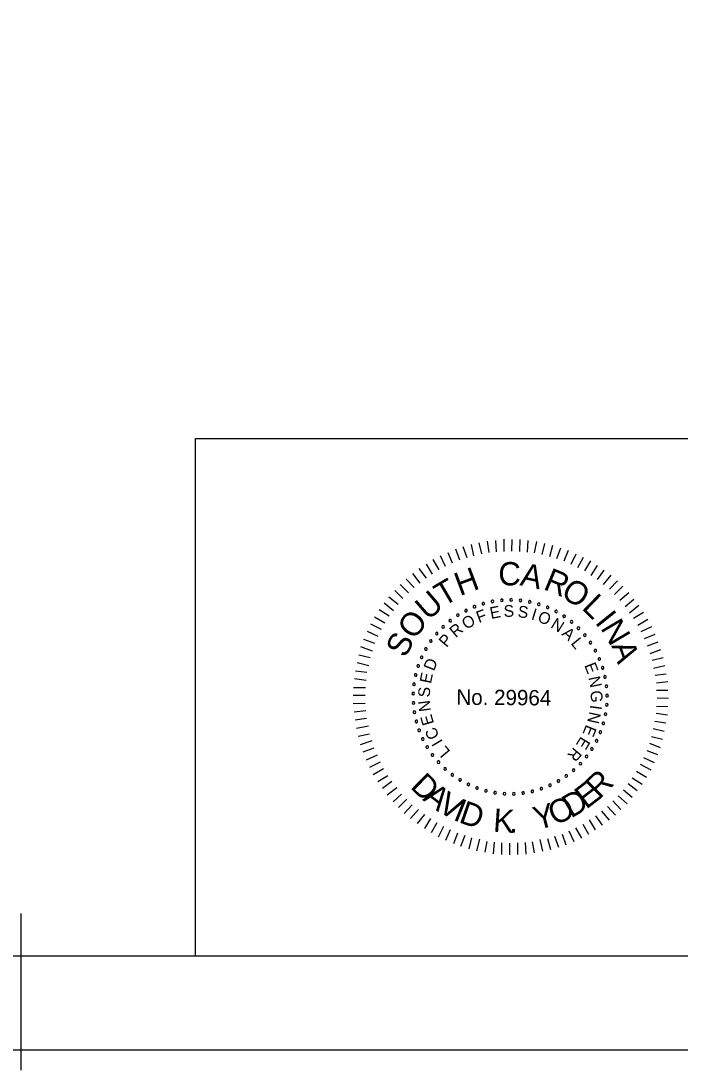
# Model space of a CAD drawing. Extents: x -133.1 to -97, y -1.8 to 20.5.
# Drawn here: x -111.44 to -107.93, y -1.8 to 3.78 of the extents above; entities that cross this region are included whole.
import ezdxf

# ---------------------------------------------------------------- set-up
doc = ezdxf.new("R2010")
doc.units = 0
for name, color, linetype in [('BR_BORDER LINES', 7, 'Continuous'), ('BR_TEXT', 7, 'Continuous'), ('Level 31', 7, 'Continuous')]:
    doc.layers.add(name, color=color, linetype=linetype)

msp = doc.modelspace()

# ---------------------------------------------------------------- linework, layer by layer
at = {"layer": 'BR_BORDER LINES'}
for p, q in [((-110.5071, 1.5591), (-105.1419, 1.5591)), ((-110.5071, -1.191), (-110.5071, 1.5591)), ((-131.3076, -1.191), (-97.6416, -1.191))]:
    msp.add_line(p, q, dxfattribs=at)
at = {"layer": 'BR_TEXT'}
for p, q in [((-108.9849, 0.9447), (-108.999, 1.0041)), ((-108.9454, 0.9521), (-108.9543, 1.0131)), ((-108.9059, 0.9561), (-108.9097, 1.017)), ((-108.8664, 0.9584), (-108.8658, 1.0227)), ((-108.8243, 0.9606), (-108.8238, 1.0224)), ((-108.7823, 0.9577), (-108.78, 1.022)), ((-108.742, 0.9548), (-108.7372, 1.0156)), ((-108.7034, 0.9501), (-108.6926, 1.011)), ((-109.1406, 0.8954), (-109.1642, 0.9514)), ((-109.1019, 0.9122), (-109.1229, 0.9708)), ((-109.0623, 0.9248), (-109.0842, 0.9824)), ((-109.0262, 0.9348), (-109.0394, 0.9958)), ((-108.6631, 0.9421), (-108.6489, 1.0012)), ((-108.622, 0.9314), (-108.606, 0.9922)), ((-108.5852, 0.9208), (-108.5633, 0.9781)), ((-108.5458, 0.9076), (-108.5239, 0.9658)), ((-109.2122, 0.8608), (-109.2426, 0.9151)), ((-109.1777, 0.8785), (-109.2039, 0.9345)), ((-108.5099, 0.8902), (-108.482, 0.9457)), ((-108.474, 0.8727), (-108.4427, 0.9282)), ((-108.4364, 0.8544), (-108.4042, 0.9082)), ((-109.3123, 0.7904), (-109.3522, 0.8405)), ((-109.2786, 0.8159), (-109.3177, 0.8668)), ((-109.2475, 0.8371), (-109.278, 0.8914)), ((-108.4031, 0.8301), (-108.3692, 0.8839)), ((-108.3699, 0.8083), (-108.3334, 0.8587)), ((-109.3745, 0.7386), (-109.4188, 0.7827)), ((-109.3451, 0.7658), (-109.3868, 0.8107)), ((-108.3375, 0.7824), (-108.2968, 0.8318)), ((-108.3059, 0.7572), (-108.2627, 0.8014)), ((-109.4039, 0.7079), (-109.4474, 0.7503)), ((-108.2779, 0.7295), (-108.2346, 0.7729)), ((-108.2498, 0.6984), (-108.2022, 0.74)), ((-109.4551, 0.6431), (-109.5046, 0.683)), ((-109.4291, 0.6763), (-109.4786, 0.7154)), ((-108.2226, 0.6664), (-108.1759, 0.7046)), ((-108.1988, 0.6327), (-108.1496, 0.6718)), ((-109.4768, 0.6141), (-109.5306, 0.6472)), ((-108.1768, 0.6034), (-108.1242, 0.6355)), ((-109.5186, 0.5432), (-109.575, 0.5711)), ((-109.5012, 0.5774), (-109.5549, 0.6096)), ((-108.1548, 0.5663), (-108.1013, 0.5976)), ((-108.137, 0.5318), (-108.0793, 0.5588)), ((-109.5361, 0.5065), (-109.5933, 0.5318)), ((-108.1193, 0.4948), (-108.0624, 0.5192)), ((-109.5659, 0.4278), (-109.6275, 0.4506)), ((-109.5536, 0.468), (-109.6117, 0.4899)), ((-108.1025, 0.456), (-108.0456, 0.477)), ((-109.5782, 0.3918), (-109.639, 0.4069)), ((-108.0891, 0.4156), (-108.0314, 0.4374)), ((-108.079, 0.3794), (-108.0189, 0.3935)), ((-109.5854, 0.3498), (-109.6479, 0.3658)), ((-108.0708, 0.3373), (-108.0106, 0.3522)), ((-109.6006, 0.2727), (-109.6624, 0.2801)), ((-109.596, 0.3138), (-109.6569, 0.3221)), ((-108.0625, 0.3012), (-108.0033, 0.3084)), ((-109.6035, 0.2333), (-109.6679, 0.2338)), ((-108.056, 0.26), (-107.995, 0.2663)), ((-109.6056, 0.1921), (-109.6682, 0.1926)), ((-108.0546, 0.2205), (-107.9945, 0.22)), ((-108.0524, 0.1793), (-107.9915, 0.1788)), ((-109.6042, 0.1492), (-109.6686, 0.148)), ((-108.0553, 0.1364), (-107.9952, 0.1342)), ((-109.602, 0.1105), (-109.6638, 0.1033)), ((-109.598, 0.0693), (-109.659, 0.0604)), ((-108.0645, 0.0566), (-108.0054, 0.0467)), ((-108.0574, 0.0978), (-107.9965, 0.0896)), ((-109.5881, 0.0297), (-109.6508, 0.0165)), ((-108.0735, 0.0172), (-108.0135, 0.003)), ((-109.5815, -0.0124), (-109.6426, -0.0265)), ((-109.5698, -0.0493), (-109.6318, -0.0703)), ((-108.0824, -0.0248), (-108.0224, -0.0398)), ((-109.5582, -0.0881), (-109.6167, -0.1091)), ((-108.107, -0.1001), (-108.0506, -0.122)), ((-108.093, -0.0615), (-108.0357, -0.0835)), ((-109.5413, -0.1251), (-109.599, -0.1521)), ((-109.5244, -0.1613), (-109.5813, -0.1909)), ((-108.1245, -0.1368), (-108.0681, -0.1647)), ((-109.5076, -0.1984), (-109.5619, -0.2297)), ((-108.1612, -0.2095), (-108.1082, -0.2417)), ((-108.1428, -0.1727), (-108.0856, -0.2032)), ((-109.4838, -0.2355), (-109.5382, -0.2668)), ((-109.4626, -0.2648), (-109.5127, -0.3013)), ((-108.2063, -0.2752), (-108.1577, -0.3125)), ((-108.1838, -0.2462), (-108.1317, -0.2784)), ((-109.4372, -0.2985), (-109.4873, -0.3376)), ((-109.4125, -0.3321), (-109.4567, -0.373)), ((-108.2306, -0.3084), (-108.1846, -0.3483)), ((-109.3836, -0.3582), (-109.4286, -0.4032)), ((-109.3547, -0.3884), (-109.3971, -0.4344)), ((-108.2869, -0.3672), (-108.2444, -0.413)), ((-108.2583, -0.3417), (-108.2115, -0.3833)), ((-109.3222, -0.4144), (-109.363, -0.4613)), ((-109.289, -0.4404), (-109.3289, -0.4882)), ((-108.3474, -0.4225), (-108.3075, -0.47)), ((-108.3155, -0.397), (-108.273, -0.4437)), ((-109.2583, -0.4622), (-109.2896, -0.5142)), ((-109.2233, -0.4847), (-109.2546, -0.5386)), ((-108.4475, -0.4911), (-108.4162, -0.5455)), ((-108.4139, -0.4691), (-108.3808, -0.5217)), ((-108.3802, -0.448), (-108.3446, -0.4963)), ((-109.1891, -0.5048), (-109.2162, -0.5603)), ((-109.1523, -0.5222), (-109.1769, -0.5778)), ((-109.1139, -0.5397), (-109.1358, -0.5962)), ((-109.0745, -0.552), (-109.0973, -0.6102)), ((-108.5974, -0.556), (-108.5764, -0.6145)), ((-108.5578, -0.5443), (-108.5368, -0.6011)), ((-108.5216, -0.5274), (-108.4947, -0.5835)), ((-108.4855, -0.5106), (-108.455, -0.5666)), ((-109.0386, -0.5644), (-109.0528, -0.6235)), ((-108.9974, -0.5716), (-109.0126, -0.6333)), ((-108.9581, -0.5831), (-108.968, -0.6413)), ((-108.9186, -0.5877), (-108.9234, -0.6494)), ((-108.8792, -0.5906), (-108.8797, -0.6524)), ((-108.8372, -0.5935), (-108.8377, -0.6544)), ((-108.7951, -0.5913), (-108.7939, -0.6531)), ((-108.7547, -0.589), (-108.7509, -0.6509)), ((-108.7161, -0.5851), (-108.7062, -0.6435)), ((-108.6756, -0.5742), (-108.6624, -0.6361)), ((-108.6344, -0.5677), (-108.6194, -0.627))]:
    msp.add_line(p, q, dxfattribs=at)
for centre, start, end in [((-109.0235, 0.6646), 21.6807, 201.6807), ((-108.9763, 0.6806), 16.1422, 196.1422), ((-108.9763, 0.6806), 196.1422, 16.1422), ((-108.9278, 0.692), 10.6038, 190.6038), ((-108.9278, 0.692), 190.6038, 10.6038), ((-108.8784, 0.6987), 5.0653, 185.0653), ((-108.8784, 0.6987), 185.0653, 5.0653), ((-108.8286, 0.7006), 359.5268, 179.5268), ((-108.8286, 0.7006), 179.5268, 359.5268), ((-108.7789, 0.6977), 173.9884, 353.9884), ((-108.7789, 0.6977), 353.9884, 173.9884), ((-108.7296, 0.69), 168.4499, 348.4499), ((-108.7296, 0.69), 348.4499, 168.4499), ((-108.6814, 0.6776), 162.9114, 342.9114), ((-108.6814, 0.6776), 342.9114, 162.9114), ((-109.1121, 0.6192), 32.7576, 212.7576), ((-109.1121, 0.6192), 212.7576, 32.7576), ((-109.0689, 0.644), 27.2191, 207.2191), ((-109.0689, 0.644), 207.2191, 27.2191), ((-109.0235, 0.6646), 201.6807, 21.6807), ((-108.6345, 0.6606), 157.373, 337.373), ((-108.6345, 0.6606), 337.373, 157.373), ((-108.5896, 0.6391), 151.8345, 331.8345), ((-108.5896, 0.6391), 331.8345, 151.8345), ((-108.5469, 0.6134), 146.2961, 326.2961), ((-108.5469, 0.6134), 326.2961, 146.2961), ((-109.1903, 0.5577), 43.8345, 223.8345), ((-109.1903, 0.5577), 223.8345, 43.8345), ((-109.1527, 0.5903), 38.2961, 218.2961), ((-109.1527, 0.5903), 218.2961, 38.2961), ((-108.5069, 0.5837), 140.7576, 320.7576), ((-108.5069, 0.5837), 320.7576, 140.7576), ((-109.2246, 0.5215), 49.373, 229.373), ((-109.2246, 0.5215), 229.373, 49.373), ((-108.4699, 0.5503), 135.2191, 315.2191), ((-108.4699, 0.5503), 315.2191, 135.2191), ((-108.4363, 0.5134), 129.6807, 309.6807), ((-108.4363, 0.5134), 309.6807, 129.6807), ((-109.282, 0.4402), 60.4499, 240.4499), ((-109.282, 0.4402), 240.4499, 60.4499), ((-109.2553, 0.4822), 54.9114, 234.9114), ((-109.2553, 0.4822), 234.9114, 54.9114), ((-108.4065, 0.4735), 124.1422, 304.1422), ((-108.4065, 0.4735), 304.1422, 124.1422), ((-109.3045, 0.3957), 65.9884, 245.9884), ((-109.3045, 0.3957), 245.9884, 65.9884), ((-108.3806, 0.4309), 118.6038, 298.6038), ((-108.3806, 0.4309), 298.6038, 118.6038), ((-108.359, 0.3861), 113.0653, 293.0653), ((-108.359, 0.3861), 293.0653, 113.0653), ((-109.3227, 0.3493), 71.5268, 251.5268), ((-109.3227, 0.3493), 251.5268, 71.5268), ((-108.3418, 0.3393), 107.5268, 287.5268), ((-108.3418, 0.3393), 287.5268, 107.5268), ((-109.3363, 0.3014), 77.0653, 257.0653), ((-109.3363, 0.3014), 257.0653, 77.0653), ((-108.3292, 0.2911), 101.9884, 281.9884), ((-108.3292, 0.2911), 281.9884, 101.9884), ((-109.3452, 0.2524), 82.6038, 262.6038), ((-109.3452, 0.2524), 262.6038, 82.6038), ((-108.3213, 0.2419), 96.4499, 276.4499), ((-108.3213, 0.2419), 276.4499, 96.4499), ((-109.3493, 0.2027), 88.1422, 268.1422), ((-109.3493, 0.2027), 268.1422, 88.1422), ((-108.3182, 0.1921), 90.9114, 270.9114), ((-108.3182, 0.1921), 270.9114, 90.9114), ((-109.3486, 0.1529), 93.6807, 273.6807), ((-109.3486, 0.1529), 273.6807, 93.6807), ((-108.3199, 0.1423), 85.373, 265.373), ((-108.3199, 0.1423), 265.373, 85.373), ((-109.3431, 0.1033), 99.2191, 279.2191), ((-109.3431, 0.1033), 279.2191, 99.2191), ((-109.3328, 0.0546), 104.7576, 284.7576), ((-109.3328, 0.0546), 284.7576, 104.7576), ((-108.3265, 0.0929), 79.8345, 259.8345), ((-108.3265, 0.0929), 259.8345, 79.8345), ((-109.3179, 0.007), 110.2961, 290.2961), ((-109.3179, 0.007), 290.2961, 110.2961), ((-108.3536, -0.0028), 68.7576, 248.7576), ((-108.3536, -0.0028), 248.7576, 68.7576), ((-108.3377, 0.0444), 74.2961, 254.2961), ((-108.3377, 0.0444), 254.2961, 74.2961), ((-109.2985, -0.0389), 115.8345, 295.8345), ((-109.2985, -0.0389), 295.8345, 115.8345), ((-108.374, -0.0483), 63.2191, 243.2191), ((-108.374, -0.0483), 243.2191, 63.2191), ((-109.2747, -0.0826), 121.373, 301.373), ((-109.2747, -0.0826), 301.373, 121.373), ((-108.3986, -0.0916), 57.6807, 237.6807), ((-108.3986, -0.0916), 237.6807, 57.6807), ((-109.2468, -0.1239), 126.9114, 306.9114), ((-109.2468, -0.1239), 306.9114, 126.9114), ((-109.2151, -0.1624), 132.4499, 312.4499), ((-109.2151, -0.1624), 312.4499, 132.4499), ((-108.4599, -0.1701), 46.6038, 226.6038), ((-108.4599, -0.1701), 226.6038, 46.6038), ((-108.4273, -0.1323), 52.1422, 232.1422), ((-108.4273, -0.1323), 232.1422, 52.1422), ((-109.1798, -0.1975), 137.9884, 317.9884), ((-109.1798, -0.1975), 317.9884, 137.9884), ((-109.1413, -0.2291), 323.5268, 143.5268), ((-108.4959, -0.2045), 41.0653, 221.0653), ((-108.4959, -0.2045), 221.0653, 41.0653), ((-109.1413, -0.2291), 143.5268, 323.5268), ((-109.0999, -0.2569), 149.0653, 329.0653), ((-109.0999, -0.2569), 329.0653, 149.0653), ((-109.056, -0.2805), 154.6038, 334.6038), ((-109.056, -0.2805), 334.6038, 154.6038), ((-108.6214, -0.2849), 24.4499, 204.4499), ((-108.577, -0.2622), 29.9884, 209.9884), ((-108.577, -0.2622), 209.9884, 29.9884), ((-108.5351, -0.2353), 35.5268, 215.5268), ((-108.5351, -0.2353), 215.5268, 35.5268), ((-109.01, -0.2997), 160.1422, 340.1422), ((-109.01, -0.2997), 340.1422, 160.1422), ((-108.9624, -0.3145), 165.6807, 345.6807), ((-108.9624, -0.3145), 345.6807, 165.6807), ((-108.9136, -0.3245), 171.2191, 351.2191), ((-108.9136, -0.3245), 351.2191, 171.2191), ((-108.8641, -0.3299), 356.7576, 176.7576), ((-108.8641, -0.3299), 176.7576, 356.7576), ((-108.8142, -0.3304), 2.2961, 182.2961), ((-108.8142, -0.3304), 182.2961, 2.2961), ((-108.7646, -0.3261), 7.8345, 187.8345), ((-108.7646, -0.3261), 187.8345, 7.8345), ((-108.7156, -0.317), 13.373, 193.373), ((-108.7156, -0.317), 193.373, 13.373), ((-108.6677, -0.3032), 18.9114, 198.9114), ((-108.6677, -0.3032), 198.9114, 18.9114), ((-108.6214, -0.2849), 204.4499, 24.4499)]:
    msp.add_arc(centre, 0.00701, start, end, dxfattribs=at)
at = {"layer": 'Level 31'}
msp.add_line((-111.4362, -0.967), (-111.4362, -1.799), dxfattribs=at)
msp.add_lwpolyline([(-133.1409, -1.691), (-97.141, -1.691), (-97.141, 20.309), (-133.1409, 20.309)], close=True, dxfattribs=at)

# ---------------------------------------------------------------- texts
at = {"layer": 'BR_TEXT'}
for s, height, rotation, p in [('C', 0.1241, 359.5482, (-108.8971, 0.7782)), ('H', 0.1241, 20.3637, (-109.1015, 0.7199)), ('A', 0.1241, 348.1981, (-108.7857, 0.779)), ('R', 0.1241, 337.4344, (-108.6624, 0.7591)), ('T', 0.1241, 30.4992, (-109.1894, 0.6624)), ('O', 0.1239, 326.5869, (-108.5702, 0.7224)), ('U', 0.1241, 40.8022, (-109.2706, 0.5876)), ('L', 0.1241, 315.9488, (-108.4576, 0.6546)), ('E', 0.0622, 11.4103, (-108.9351, 0.5987)), ('S', 0.0622, 2.208, (-108.8672, 0.6097)), ('S', 0.0622, 352.6608, (-108.796, 0.6095)), ('O', 0.1241, 52.0267, (-109.3451, 0.4837)), ('O', 0.0622, 30.8477, (-109.0676, 0.541)), ('F', 0.0622, 20.6127, (-109.0002, 0.577)), ('I', 0.0622, 343.1136, (-108.7257, 0.5975)), ('O', 0.0622, 338.4392, (-108.6923, 0.5873)), ('I', 0.1241, 308.6613, (-108.3862, 0.5803)), ('R', 0.0622, 40.3949, (-109.1237, 0.4971)), ('N', 0.0622, 328.2042, (-108.6227, 0.5559)), ('N', 0.1241, 300.7037, (-108.3556, 0.5509)), ('S', 0.1239, 63.2511, (-109.3905, 0.3881)), ('P', 0.0622, 49.9421, (-109.1718, 0.4445)), ('A', 0.0622, 318.657, (-108.5637, 0.5159)), ('L', 0.0622, 309.4546, (-108.5139, 0.4686)), ('A', 0.1241, 289.4792, (-108.2964, 0.4579)), ('D', 0.0622, 69.0364, (-109.2388, 0.3192)), ('E', 0.0622, 291.049, (-108.44, 0.3533)), ('E', 0.0622, 78.2388, (-109.2553, 0.2526)), ('N', 0.0622, 281.8466, (-108.4179, 0.2882)), ('S', 0.0622, 87.786, (-109.2611, 0.1815)), ('No. 29964', 0.08175, 359.5268, (-109.1199, 0.1431)), ('G', 0.0622, 272.2995, (-108.4061, 0.2179)), ('N', 0.0622, 97.3332, (-109.2549, 0.1105)), ('I', 0.0622, 262.4084, (-108.4065, 0.1441)), ('E', 0.0622, 106.5355, (-109.2379, 0.044)), ('N', 0.0622, 257.7339, (-108.411, 0.1095)), ('C', 0.0622, 116.4266, (-109.208, -0.0235)), ('E', 0.0622, 248.1867, (-108.4291, 0.0406)), ('I', 0.0622, 121.1011, (-109.1899, -0.0534)), ('E', 0.0622, 238.9844, (-108.457, -0.0222)), ('L', 0.0622, 129.9595, (-109.1493, -0.1056)), ('R', 0.0622, 229.782, (-108.4947, -0.0797)), ('D', 0.1236, 315.4053, (-109.3698, -0.2962)), ('R', 0.1236, 44.5947, (-108.3589, -0.3617)), ('E', 0.1236, 37.5339, (-108.4295, -0.4156)), ('A', 0.1236, 322.8377, (-109.3032, -0.3618)), ('V', 0.1236, 330.5179, (-109.226, -0.42)), ('D', 0.1236, 30.1015, (-108.5104, -0.4626)), ('I', 0.1236, 338.1981, (-109.1418, -0.4674)), ('D', 0.1236, 340.7995, (-109.1119, -0.4808)), ('Y', 0.1236, 14.8649, (-108.6915, -0.5241)), ('O', 0.1236, 22.4212, (-108.5997, -0.4996)), ('K', 0.1236, 356.098, (-108.9267, -0.5314)), ('.', 0.1236, 3.1588, (-108.838, -0.5377))]:
    msp.add_text(s, height=height, rotation=rotation, dxfattribs=at).set_placement(p)

doc.saveas('drawing.dxf')
